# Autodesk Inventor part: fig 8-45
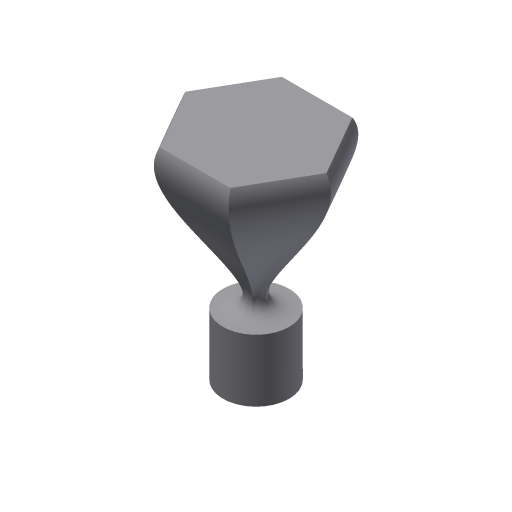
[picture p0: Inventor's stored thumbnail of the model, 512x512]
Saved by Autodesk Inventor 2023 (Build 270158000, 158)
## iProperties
Created: 2004-05
Part Number: fig 8-45
Document SubType Name: Modeling
Designer: CADCIM Technologies
Manufacturer: Standard
Standards Organization: Custom
Density: 1 g/cm^3
Material: Generic
Appearance: Default
Author: CADCIM Technologies
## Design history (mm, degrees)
sketch "Sketch1"
  geometry: C1 r 16.344 at (0, 0)
  constraints: 1 centre point
extrude "Extrusion1" new body sketch "Sketch1" distance "d0" = 30.75; taper "d1" = 0 deg
workplane "Work Plane1"
sketch "Sketch2"
  geometry: L1 (34.788, 0)-(17.394, -30.128); L2 (17.394, -30.128)-(-17.394, -30.128); L3 (-17.394, -30.128)-(-34.788, 0); L4 (-34.788, 0)-(-17.394, 30.128); L5 (-17.394, 30.128)-(17.394, 30.128); L6 (17.394, 30.128)-(34.788, 0); 2 further points
  constraints: 12 end point, 1 coincident, 12 other
loft "Loft2" sketch "Sketch2" dims "d9" = 15, "d10" = 90 deg, "d11" = 80, "d12" = 120 deg
  node "Edges2"
body "Solid1"
other parameters: "d2" = 75
